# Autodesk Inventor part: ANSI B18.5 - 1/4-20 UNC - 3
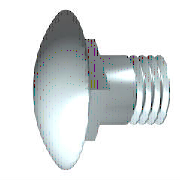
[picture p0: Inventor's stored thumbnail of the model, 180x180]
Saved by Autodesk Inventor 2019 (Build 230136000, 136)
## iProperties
IsCustomPart: 0
Created: 2018-01
Part Number: ANSI B18.5 - 1/4-20 UNC - 3
Material: Steel, Mild
Description: Round Head Short Square Neck Bolt
Document SubType Name: Modeling
Standard: ANSI B18.5
Designer: patrick
Standard Revision: 2012
Standards Organization: ANSI
Language: en-US
Size Designation: 1/4-20 UNC - 3
Categories: <MemberInstance><Categories><Category DisplayName="Fasteners" InternalName="e4da775c-781d-43d5-af7c-5136215cf5a6" Mnemonic="FSTN"><Category DisplayName="Bolts"
Density: 7.85 g/cm^3
Appearance: Semi-Polished
Author: patrick
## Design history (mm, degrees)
body "Solid1"
sketch "Sketch1"
  geometry: L1 (-3.683, 0)-(76.2, 0); L2 (76.2, 0)-(76.2, 3.175); L3 (0, 3.175)-(0, 7.544); L4 (0, 7.544)-(-0.142, 7.544); L5 (-0.142, 7.544)-(-0.142, 0); L6 (-20.669, 0)-(92.345, 0) reference; L7 (0, -1.588)-(0, 9.526) reference; L8 (55.88, 3.175)-(57.15, 3.175); L9 (55.88, 3.175)-(3.15, 3.175); L10 (3.15, 3.175)-(3.15, 3.175); L11 (76.2, 3.175)-(57.15, 3.175); L12 (3.15, 3.175)-(0, 3.175); L13 (3.15, 3.175)-(57.15, 3.175); A1 r 9.807 centre (6.124, 0) between (-0.142, 7.544) and (-3.683, 0)
  constraints: 22 end point, 5 parallel, 3 collinear, 2 perpendicular, 2 point on circle, 2 point on line, 1 centre point, 1 horizontal
  dimensions: "d0" = 76.2 distance between parallel lines of L2 L3 (= NLG); "d1" = 3.683 distance from line of L1.start L3 (= KOH); "d2" = 9.80694 radius of A1 (= KR); "d3" = 15.0876 diameter of L4 L1 (= KOD); "d8" = 6.35 diameter of L9 L1 (= BDM); "d9" = 1.27 distance of L8.end L8.start (= GAL); "d14" = 3.1496 distance between parallel lines of L10 L3 (= SD); "d15" = 55.88 distance from line of L8.start L3 (= -GEL + NLG - GAL); "d20" = 6.35 diameter of L11 L1 (= GD)
revolve "Body" stored, may be unused: angle "d5" = 90 deg
sketch "Sketch2"
  geometry: L1 (0, -10.561)-(0, 10.561) reference; L2 (10.561, 0)-(-10.561, 0) reference; L3 (-3.302, 3.302)-(3.302, 3.302); L4 (3.302, 3.302)-(3.302, -3.302); L5 (3.302, -3.302)-(-3.302, -3.302); L6 (-3.302, -3.302)-(-3.302, 3.302); L7 (0, 3.302)-(0, -3.302); L8 (-3.302, 0)-(3.302, 0); C1 r 3.175 at (0, 0) reference
  constraints: 12 end point, 4 midpoint, 2 collinear, 2 parallel, 1 horizontal, 1 perpendicular
  dimensions: "d10" = 6.604 distance of L4.end L5.end (= SD2); "d11" = 6.604 distance of L5.end L3.start (= SD2)
extrude "Neck" join sketch "Sketch2" distance "d12" = 3.1496 (= SD); taper "d13" = 0 deg
workplane "Work Plane2"
revolve "Revolution4" stored, may be unused: angle "d35" = 90 deg
feature "Thread" dims "d6" = 19.05 (= GEL), "d7" = 0
chamfer "Chamfer1" distance "d16" = 1.17475 (= -0.5 x SPD + 0.5 x GD); stored, may be unused: second distance "d17" = 0.0254 (= GUL), angle "d31" = 45 deg
workplane "Work Plane1"
fillet "Fillet1" dims "d38" = 0.7874 (= Q)
fillet "Fillet2" dims "d39" = 0.7874 (= R)
sketch "Sketch4"
  geometry: L1 (3.15, 9.339)-(3.15, 4.67) reference; L2 (-19.66, 4.67)-(92.177, 4.67) reference; L3 (3.15, 7.845)-(76.2, 7.845) reference; L4 (3.15, 7.845)-(3.15, 7.845); L5 (3.15, 7.845)-(3.15, 9.339); L6 (2.287, 9.339)-(3.15, 7.845); L7 (2.287, 9.339)-(3.15, 9.339)
  constraints: 8 end point, 2 perpendicular, 1 collinear, 1 point on line
  dimensions: "d37" = 30 deg angle of L1 L6
other parameters: "GD" = 6.35 (= NND) [user parameter; used in 3 equation terms], "NLG" = 76.2 [user parameter; used in 2 equation terms], "GEL" = 19.05 [user parameter; used in 2 equation terms], "KOD" = 15.0876 [user parameter; used in 2 equation terms], "KOH" = 3.683 [user parameter; used in 1 equation term], "GAL" = 1.27 [user parameter; used in 4 equation terms], "GUL" = 0.0254 [user parameter; used in 1 equation term], "SPD" = 4.0005 (= -1.35 x GAL + 0.9 x NND) [user parameter; used in 1 equation term], "KR" = 9.80694 (= 0.65 x KOD) [user parameter; used in 1 equation term], "BDM" = 6.35 (= NND) [user parameter; used in 1 equation term], "SD" = 3.1496 [user parameter; used in 2 equation terms], "SD2" = 6.604 [user parameter; used in 2 equation terms], "d4" = 6.35 (= GD), "d19" = 0, "d32" = 0, "d33" = 0, "R" = 0.7874 [user parameter; used in 1 equation term], "Q" = 0.7874 [user parameter; used in 1 equation term], "KKR" = 0.7874 [user parameter], "THREADDIA" = 6.35 [user parameter], "TOA" = 30 deg [user parameter], "ANG" = 15 deg [user parameter], "PTC" = 1.27 (computed from TPU) [user parameter], "NND" = 6.35 [user parameter; used in 4 equation terms], "GD1" = 4.445 (= NND - 1.5 x GAL) [user parameter]
